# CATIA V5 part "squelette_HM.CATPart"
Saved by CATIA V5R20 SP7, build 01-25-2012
Part number: squelette_HM
Publications: "barre_HM", "K'", "KK'", "axe.pivot.H", "axe.pivot.M", "axe.pivot.K", "Plan.pivots"
Bounding box of the stored display mesh (mm): x -22 to 18, y 0 to 0, z -9.5 to 25.5
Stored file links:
  F:\IAO_Renouveau\squelette_HM.CATPart
  F:\IAO_Renouveau\squelette.CATProduct
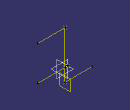
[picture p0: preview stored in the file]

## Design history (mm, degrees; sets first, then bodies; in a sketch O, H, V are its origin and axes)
Set1
  Point1 "H": linked copy from another document
  Point2 "M": linked copy from another document
  Plane1 "plan.-2": linked copy from another document
  Point3 "K": linked copy from another document
  Plane2 "Plan.xy": linked copy from another document
Set2
  Line1 "barre_HM": type PtPt, FirstPoint Point1, SecondPoint Point2, Support Plane1
  Point4 "K'": type OnCurve, Support Line1, RefPoint Point1, Length 9.5
  Line2 "KK'": type PtPt, FirstPoint Point4, SecondPoint Point3, Support Plane2
  Line3 "axe.pivot.H": type Normal, RefPoint Point1, RefSkin Plane1, Start 0, End 20
  Line4 "axe.pivot.M": type Normal, RefPoint Point2, RefSkin Plane1, Start 0, End 20
  Line5 "axe.pivot.K": type Normal, RefPoint Point4, RefSkin Plane1, Start 0, End 20
  Plane3 "Plan.pivots": type Offset, RefPlane Plane1, Offset 0
Body1 (main body)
